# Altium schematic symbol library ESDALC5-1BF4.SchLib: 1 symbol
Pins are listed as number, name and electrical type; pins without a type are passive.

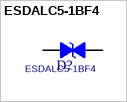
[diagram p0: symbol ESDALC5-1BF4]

## ESDALC5-1BF4
designator D?
footprint ST_0201B-F4
pins: 1, 2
